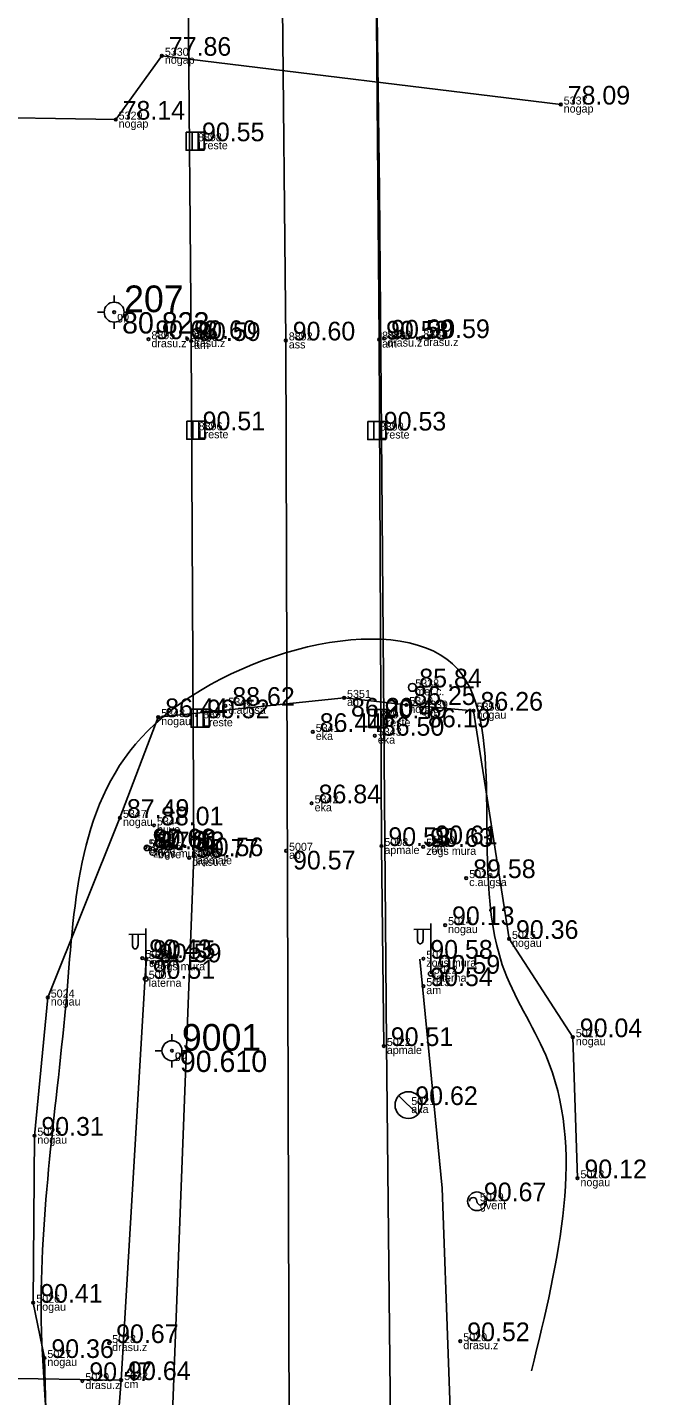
# Model space of a CAD drawing. Extents: x 614911 to 615803, y 262110 to 264311.
# Drawn here: x 615625.2 to 615648.4, y 263133.6 to 263184.9 of the extents above; entities that cross this region are included whole.
import ezdxf

# ---------------------------------------------------------------- set-up
doc = ezdxf.new("R2010")
doc.units = 0
for name, color, linetype in [('Default', 7, 'Continuous'), ('Level 12', 7, 'Continuous'), ('Level 14', 7, 'Continuous'), ('Level 19', 7, 'Continuous'), ('Level 27', 7, 'Continuous'), ('Level 31', 7, 'Continuous'), ('Level 37', 7, 'Continuous'), ('Level 44', 7, 'Continuous'), ('Level 48', 7, 'Continuous'), ('Level 53', 7, 'Continuous'), ('Level 54', 7, 'Continuous'), ('Level 57', 7, 'Continuous'), ('Level 58', 7, 'Continuous'), ('Level 7', 7, 'Continuous')]:
    doc.layers.add(name, color=color, linetype=linetype)

msp = doc.modelspace()

# ---------------------------------------------------------------- linework, layer by layer
at = {"layer": 'Default'}
for points in [[(615642.111, 263047.236), (615640.427, 263062.246), (615639.699, 263075.455), (615639.466, 263087.731), (615639.08, 263107.594), (615638.669, 263146.776), (615638.411, 263178.773), (615638.281, 263188.183)], [(615640.757, 263141.353), (615639.919, 263149.948)], [(615640.757, 263141.353), (615640.998, 263134.817), (615641.077, 263132.377), (615643.967, 263132.511)]]:
    msp.add_lwpolyline(points, dxfattribs=at)
msp.add_spline([(615625.966, 263122.745), (615626.114, 263129.516), (615625.726, 263136.404), (615626.677, 263148.613), (615629.722, 263158.508), (615641.149, 263161.013), (615643.012, 263149.736), (615644.64, 263146.351), (615644.11, 263134.516)], degree=3, dxfattribs=at)
at = {"layer": 'Level 12'}
for p, q in [((615639.13, 263144.823), (615639.848, 263144.127)), ((615639.489, 263144.475), (615639.488, 263144.474))]:
    msp.add_line(p, q, dxfattribs=at)
msp.add_circle((615639.489, 263144.475), 0.5, dxfattribs=at)
at = {"layer": 'Level 14'}
msp.add_circle((615639.638, 263160.134), 0.148, dxfattribs=at)
at = {"layer": 'Level 19'}
for p, q in [((615628.459, 263174.576), (615628.459, 263174.826)), ((615627.834, 263174.201), (615628.084, 263174.201)), ((615628.834, 263174.201), (615629.084, 263174.201)), ((615628.459, 263173.576), (615628.459, 263173.826)), ((615630.625, 263146.889), (615630.625, 263147.139)), ((615630, 263146.514), (615630.25, 263146.514)), ((615631, 263146.514), (615631.25, 263146.514)), ((615630.625, 263145.889), (615630.625, 263146.139))]:
    msp.add_line(p, q, dxfattribs=at)
for centre, radius in [((615628.459, 263174.201), 0.375), ((615628.459, 263174.201), 0.05), ((615630.625, 263146.514), 0.375), ((615630.625, 263146.514), 0.05)]:
    msp.add_circle(centre, radius, dxfattribs=at)
at = {"layer": 'Level 27'}
msp.add_circle((615642.061, 263140.868), 0.35, dxfattribs=at)
for centre, start, end in [((615641.921, 263140.868), 0, 180), ((615642.201, 263140.868), 180, 0)]:
    msp.add_arc(centre, 0.14, start, end, dxfattribs=at)
at = {"layer": 'Level 31'}
for points in [[(615645.203, 263181.984), (615630.246, 263183.814), (615628.514, 263181.419), (615622.47, 263181.52), (615621.763, 263178.82), (615619.334, 263173.437), (615618.468, 263173.209), (615614.263, 263169.507), (615607.963, 263162.509), (615614.672, 263141.896), (615612.332, 263134.683)], [(615639.412, 263159.474), (615637.078, 263159.739), (615630.111, 263159.019)], [(615639.412, 263159.474), (615641.935, 263159.261), (615643.264, 263150.705), (615645.656, 263147.02), (615645.831, 263141.731)], [(615630.111, 263159.019), (615628.675, 263155.243), (615625.969, 263148.507), (615625.467, 263143.326), (615625.424, 263137.065), (615625.842, 263134.993), (615625.948, 263131.109), (615625.2, 263127.266), (615625.864, 263116.003), (615625.339, 263108.896), (615618.12, 263017.928), (615614.008, 263002.211), (615611.608, 262992.724), (615610.318, 262984.066), (615604.711, 262969.009), (615598.026, 262946.805), (615590.694, 262924.523), (615584.099, 262903.018), (615578.016, 262882.248), (615571.57, 262862.909), (615571.479, 262861.254), (615568.795, 262854.862), (615562.238, 262831.156), (615556.487, 262814.508)]]:
    msp.add_lwpolyline(points, dxfattribs=at)
at = {"layer": 'Level 37'}
for p, q in [((615634.894, 263173.142), (615635.097, 263105.763)), ((615616.193, 263134.355), (615628.721, 263134.164))]:
    msp.add_line(p, q, dxfattribs=at)
for points in [[(615636.517, 263431.183), (615636.595, 263421.289), (615636.665, 263411.593), (615636.806, 263386.87), (615636.931, 263375.725), (615636.948, 263365.501), (615637.059, 263355.344), (615637.134, 263343.807), (615637.167, 263335.039), (615637.241, 263325.081), (615637.336, 263313.942), (615637.374, 263306.112), (615637.482, 263292.409), (615637.574, 263278.5), (615637.654, 263266.567), (615637.756, 263250.366), (615637.867, 263239.792), (615637.928, 263229.314), (615638.03, 263218.463), (615638.11, 263207.891), (615638.19, 263197.069), (615638.393, 263173.174)], [(615629.566, 263431.01), (615629.603, 263421.222), (615629.627, 263411.526), (615629.82, 263386.162), (615629.901, 263376.196), (615629.953, 263365.331), (615630.032, 263355.531), (615630.094, 263343.723), (615630.15, 263334.743), (615630.222, 263324.988), (615630.324, 263314.046), (615630.353, 263305.884), (615630.476, 263292.497), (615630.569, 263278.595), (615630.639, 263268.073), (615630.767, 263250.13), (615630.888, 263239.998), (615630.949, 263229.062), (615631.015, 263218.772), (615631.067, 263208.389), (615631.123, 263199.177), (615631.345, 263173.122)], [(615634.894, 263173.142), (615634.754, 263186.919), (615634.625, 263199.339), (615634.598, 263208.099), (615634.519, 263218.105)], [(615631.345, 263173.122), (615631.449, 263153.804), (615629.561, 263104.56), (615625.716, 263040.842), (615623.595, 263025.101), (615622.447, 263017.915), (615619.741, 263006.709), (615615.254, 262992.037), (615607.495, 262968.204)], [(615638.393, 263173.174), (615638.479, 263154.188), (615638.57, 263146.689)], [(615629.654, 263149.948), (615628.721, 263134.164), (615628.583, 263132.388), (615627.854, 263104.61), (615621.91, 263025.585), (615621.904, 263025.311), (615619.521, 263012.239), (615619.398, 263011.725), (615613.627, 262992.503), (615605.986, 262968.61), (615598.735, 262946.405), (615591.778, 262924.107), (615585.103, 262902.604), (615578.685, 262882.008), (615572.188, 262861.032), (615562.921, 262830.982), (615557.662, 262813.841), (615551.445, 262793.883), (615545.378, 262774.577), (615544.847, 262773.643)]]:
    msp.add_lwpolyline(points, dxfattribs=at)
at = {"layer": 'Level 44'}
for p, q in [((615629.642, 263149.21), (615629.642, 263151.093)), ((615640.33, 263151.065), (615639.695, 263151.06)), ((615639.83, 263151.061), (615639.83, 263150.669)), ((615640.04, 263151.063), (615640.04, 263150.669)), ((615640.33, 263149.398), (615640.33, 263151.281)), ((615629.642, 263150.877), (615629.007, 263150.872)), ((615629.142, 263150.873), (615629.142, 263150.481)), ((615629.352, 263150.875), (615629.352, 263150.481))]:
    msp.add_line(p, q, dxfattribs=at)
for centre in [(615640.33, 263149.398), (615629.642, 263149.21)]:
    msp.add_circle(centre, 0.09, dxfattribs=at)
for centre in [(615629.247, 263150.481), (615639.935, 263150.669)]:
    msp.add_ellipse(centre, major_axis=(0, 0.151), ratio=0.695971, start_param=1.570796, end_param=4.712389, dxfattribs=at)
at = {"layer": 'Level 48'}
for p, q in [((615631.377, 263180.947), (615631.377, 263180.272)), ((615631.602, 263180.947), (615631.602, 263180.272)), ((615631.402, 263170.112), (615631.402, 263169.437)), ((615631.627, 263170.112), (615631.627, 263169.437)), ((615638.194, 263170.101), (615638.194, 263169.426)), ((615638.419, 263170.101), (615638.419, 263169.426)), ((615631.566, 263159.314), (615631.566, 263158.639)), ((615631.791, 263159.314), (615631.791, 263158.639)), ((615638.226, 263159.309), (615638.226, 263158.634)), ((615638.451, 263159.309), (615638.451, 263158.634))]:
    msp.add_line(p, q, dxfattribs=at)
for points in [[(615631.152, 263180.947), (615631.827, 263180.947), (615631.827, 263180.272), (615631.152, 263180.272)], [(615631.177, 263170.112), (615631.852, 263170.112), (615631.852, 263169.437), (615631.177, 263169.437)], [(615637.969, 263170.101), (615638.644, 263170.101), (615638.644, 263169.426), (615637.969, 263169.426)], [(615631.341, 263159.314), (615632.016, 263159.314), (615632.016, 263158.639), (615631.341, 263158.639)], [(615638.001, 263159.309), (615638.676, 263159.309), (615638.676, 263158.634), (615638.001, 263158.634)]]:
    msp.add_lwpolyline(points, close=True, dxfattribs=at)
at = {"layer": 'Level 57'}
for centre in [(615630.246, 263183.814), (615645.203, 263181.984), (615628.514, 263181.419), (615629.743, 263173.187), (615631.2, 263173.193), (615631.345, 263173.122), (615634.894, 263173.142), (615638.393, 263173.174), (615638.583, 263173.21), (615639.941, 263173.23), (615637.078, 263159.739), (615632.627, 263159.443), (615639.412, 263159.474), (615639.966, 263159.336), (615641.935, 263159.261), (615630.111, 263159.019), (615635.905, 263158.464), (615638.233, 263158.322), (615635.863, 263155.788), (615628.675, 263155.243), (615629.952, 263154.961), (615629.639, 263154.137), (615629.81, 263154.061), (615629.989, 263154.027), (615634.904, 263154.008), (615638.479, 263154.188), (615640.048, 263154.156), (615640.236, 263154.253), (615631.269, 263153.745), (615631.449, 263153.804), (615641.659, 263152.984), (615640.866, 263151.222), (615643.264, 263150.705), (615629.513, 263149.984), (615629.654, 263149.948), (615640.051, 263149.963), (615629.88, 263149.826), (615640.051, 263148.934), (615625.969, 263148.507), (615645.656, 263147.02), (615638.57, 263146.689), (615625.467, 263143.326), (615645.831, 263141.731), (615625.424, 263137.065), (615628.271, 263135.552), (615641.437, 263135.623), (615625.842, 263134.993), (615627.266, 263134.128), (615628.721, 263134.164)]:
    msp.add_circle(centre, 0.05, dxfattribs=at)
at = {"layer": 'Level 58'}
for centre in [(615630.246, 263183.814), (615645.203, 263181.984), (615628.514, 263181.419), (615629.743, 263173.187), (615631.2, 263173.193), (615631.345, 263173.122), (615634.894, 263173.142), (615638.393, 263173.174), (615638.583, 263173.21), (615639.941, 263173.23), (615637.078, 263159.739), (615632.627, 263159.443), (615639.412, 263159.474), (615639.966, 263159.336), (615641.935, 263159.261), (615630.111, 263159.019), (615635.905, 263158.464), (615638.233, 263158.322), (615635.863, 263155.788), (615628.675, 263155.243), (615629.952, 263154.961), (615629.639, 263154.137), (615629.81, 263154.061), (615629.989, 263154.027), (615634.904, 263154.008), (615638.479, 263154.188), (615640.048, 263154.156), (615640.236, 263154.253), (615631.269, 263153.745), (615631.449, 263153.804), (615641.659, 263152.984), (615640.866, 263151.222), (615643.264, 263150.705), (615629.513, 263149.984), (615629.654, 263149.948), (615640.051, 263149.963), (615629.88, 263149.826), (615640.051, 263148.934), (615625.969, 263148.507), (615645.656, 263147.02), (615638.57, 263146.689), (615625.467, 263143.326), (615645.831, 263141.731), (615625.424, 263137.065), (615628.271, 263135.552), (615641.437, 263135.623), (615625.842, 263134.993), (615627.266, 263134.128), (615628.721, 263134.164)]:
    msp.add_circle(centre, 0.05, dxfattribs=at)
at = {"layer": 'Level 7'}
msp.add_circle((615629.683, 263154.115), 0.1, dxfattribs=at)

# ---------------------------------------------------------------- texts
at = {"layer": 'Level 19'}
for s, height, p in [(' 207', 1, (615628.459, 263174.201)), (' 80.823', 0.8, (615628.459, 263173.401)), (' 9001', 1, (615630.625, 263146.514)), (' 90.610', 0.8, (615630.625, 263145.714))]:
    msp.add_text(s, height=height, dxfattribs=at).set_placement(p)
at = {"layer": 'Level 27'}
msp.add_text(' 90.67', height=0.7, dxfattribs=at).set_placement((615642.061, 263140.868))
at = {"layer": 'Level 48'}
for s, p in [(' 90.55', (615631.49, 263180.609)), (' 90.51', (615631.515, 263169.774)), (' 90.53', (615638.307, 263169.763)), (' 90.52', (615631.679, 263158.976)), (' 90.49', (615638.339, 263158.971))]:
    msp.add_text(s, height=0.7, dxfattribs=at).set_placement(p)
at = {"layer": 'Level 53'}
for s, p in [(' nogap', (615630.246, 263183.514)), (' nogap', (615645.203, 263181.684)), (' nogap', (615628.514, 263181.119)), (' Lreste', (615631.49, 263180.309)), (' gp', (615628.459, 263173.901)), (' drasu.z', (615629.743, 263172.887)), (' drasu.z', (615631.2, 263172.893)), (' am', (615631.345, 263172.822)), (' ass', (615634.894, 263172.842)), (' am', (615638.393, 263172.874)), (' drasu.z', (615638.583, 263172.91)), (' drasu.z', (615639.941, 263172.93)), (' Lreste', (615631.515, 263169.474)), (' Lreste', (615638.307, 263169.463)), (' met.c.', (615639.638, 263159.834)), (' c.augsa', (615632.627, 263159.143)), (' ap', (615637.078, 263159.439)), (' nogau', (615639.412, 263159.174)), (' ap', (615639.966, 263159.036)), (' nogau', (615641.935, 263158.961)), (' nogau', (615630.111, 263158.719)), (' Lreste', (615631.679, 263158.676)), (' Lreste', (615638.339, 263158.671)), (' eka', (615635.905, 263158.164)), (' eka', (615638.233, 263158.022)), (' eka', (615635.863, 263155.488)), (' nogau', (615628.675, 263154.943)), (' buve', (615629.952, 263154.661)), (' cm', (615629.639, 263153.837)), (' el.iev', (615629.683, 263153.815)), (' buve', (615629.989, 263153.727)), (' apmale', (615638.479, 263153.888)), (' zogs mura', (615640.048, 263153.856)), (' cm', (615640.236, 263153.953)), (' zogs mura', (615629.81, 263153.761)), (' drasu.z', (615631.269, 263153.445)), (' apmale', (615631.449, 263153.504)), (' ap', (615634.904, 263153.708)), (' c.augsa', (615641.659, 263152.684)), (' nogau', (615640.866, 263150.922)), (' nogau', (615643.264, 263150.405)), (' nogau', (615629.513, 263149.684)), (' cm', (615629.654, 263149.648)), (' zogs mura', (615629.88, 263149.526)), (' zogs mura', (615640.051, 263149.663)), (' laterna', (615629.642, 263148.91)), (' laterna', (615640.33, 263149.098)), (' nogau', (615625.969, 263148.207)), (' am', (615640.051, 263148.634)), (' nogau', (615645.656, 263146.72)), (' gp', (615630.625, 263146.214)), (' pp', (615630.625, 263146.214)), (' apmale', (615638.57, 263146.389)), (' aka', (615639.489, 263144.175)), (' nogau', (615625.467, 263143.026)), (' nogau', (615645.831, 263141.431)), (' gvent', (615642.061, 263140.568)), (' nogau', (615625.424, 263136.765)), (' drasu.z', (615641.437, 263135.323)), (' drasu.z', (615628.271, 263135.252)), (' nogau', (615625.842, 263134.693)), (' drasu.z', (615627.266, 263133.828)), (' cm', (615628.721, 263133.864))]:
    msp.add_text(s, height=0.3, dxfattribs=at).set_placement(p)
at = {"layer": 'Level 54'}
for s, p in [(' 5330', (615630.246, 263183.814)), (' 5337', (615645.203, 263181.984)), (' 5329', (615628.514, 263181.419)), (' 8898', (615631.49, 263180.609)), (' 8895', (615629.743, 263173.187)), (' 8894', (615631.2, 263173.193)), (' 8893', (615631.345, 263173.122)), (' 8892', (615634.894, 263173.142)), (' 8889', (615638.393, 263173.174)), (' 8888', (615638.583, 263173.21)), (' 8887', (615639.941, 263173.23)), (' 8896', (615631.515, 263169.774)), (' 8890', (615638.307, 263169.763)), (' 5338', (615639.638, 263160.134)), (' 5340', (615632.627, 263159.443)), (' 5351', (615637.078, 263159.739)), (' 5349', (615639.412, 263159.474)), (' 5348', (615630.111, 263159.019)), (' 8897', (615631.679, 263158.976)), (' 8891', (615638.339, 263158.971)), (' 5339', (615639.966, 263159.336)), (' 5350', (615641.935, 263159.261)), (' 5341', (615635.905, 263158.464)), (' 5343', (615638.233, 263158.322)), (' 5342', (615635.863, 263155.788)), (' 5347', (615628.675, 263155.243)), (' 5344', (615629.952, 263154.961)), (' 5010', (615640.236, 263154.253)), (' 5004', (615629.639, 263154.137)), (' 5346', (615629.683, 263154.115)), (' 5005', (615629.81, 263154.061)), (' 5345', (615629.989, 263154.027)), (' 5003', (615631.269, 263153.745)), (' 5006', (615631.449, 263153.804)), (' 5007', (615634.904, 263154.008)), (' 5008', (615638.479, 263154.188)), (' 5009', (615640.048, 263154.156)), (' 5016', (615641.659, 263152.984)), (' 5014', (615640.866, 263151.222)), (' 5015', (615643.264, 263150.705)), (' 5023', (615629.513, 263149.984)), (' 5002', (615629.654, 263149.948)), (' 5000', (615629.88, 263149.826)), (' 5011', (615640.051, 263149.963)), (' 5001', (615629.642, 263149.21)), (' 5012', (615640.33, 263149.398)), (' 5013', (615640.051, 263148.934)), (' 5024', (615625.969, 263148.507)), (' 5022', (615638.57, 263146.689)), (' 5017', (615645.656, 263147.02)), (' 5021', (615639.489, 263144.475)), (' 5025', (615625.467, 263143.326)), (' 5018', (615645.831, 263141.731)), (' 5019', (615642.061, 263140.868)), (' 5026', (615625.424, 263137.065)), (' 5028', (615628.271, 263135.552)), (' 5020', (615641.437, 263135.623)), (' 5027', (615625.842, 263134.993)), (' 5029', (615627.266, 263134.128)), (' 5032', (615628.721, 263134.164))]:
    msp.add_text(s, height=0.3, dxfattribs=at).set_placement(p)
at = {"layer": 'Level 58'}
for s, p in [(' 77.86', (615630.246, 263183.814)), (' 78.09', (615645.203, 263181.984)), (' 78.14', (615628.514, 263181.419)), (' 90.63', (615629.743, 263173.187)), (' 90.60', (615631.2, 263173.193)), (' 90.59', (615631.345, 263173.122)), (' 90.60', (615634.894, 263173.142)), (' 90.53', (615638.393, 263173.174)), (' 90.59', (615638.583, 263173.21)), (' 90.59', (615639.941, 263173.23)), (' 85.84', (615639.638, 263160.134)), (' 86.44', (615630.111, 263159.019)), (' 88.62', (615632.627, 263159.443)), (' 86.20', (615637.078, 263159.039)), (' 86.25', (615639.412, 263159.474)), (' 86.26', (615641.935, 263159.261)), (' 86.44', (615635.905, 263158.464)), (' 86.19', (615639.966, 263158.636)), (' 86.50', (615638.233, 263158.322)), (' 86.84', (615635.863, 263155.788)), (' 87.49', (615628.675, 263155.243)), (' 88.01', (615629.952, 263154.961)), (' 90.60', (615629.639, 263154.137)), (' 87.86', (615629.683, 263154.115)), (' 90.61', (615629.81, 263154.061)), (' 87.92', (615629.989, 263154.027)), (' 90.53', (615638.479, 263154.188)), (' 90.63', (615640.048, 263154.156)), (' 90.61', (615640.236, 263154.253)), (' 90.77', (615631.269, 263153.745)), (' 90.56', (615631.449, 263153.804)), (' 90.57', (615634.904, 263153.308)), (' 89.58', (615641.659, 263152.984)), (' 90.13', (615640.866, 263151.222)), (' 90.36', (615643.264, 263150.705)), (' 90.43', (615629.513, 263149.984)), (' 90.55', (615629.654, 263149.948)), (' 90.59', (615629.88, 263149.826)), (' 90.58', (615640.051, 263149.963)), (' 90.59', (615640.33, 263149.398)), (' 90.51', (615629.642, 263149.21)), (' 90.54', (615640.051, 263148.934)), (' 90.51', (615638.57, 263146.689)), (' 90.04', (615645.656, 263147.02)), (' 90.62', (615639.489, 263144.475)), (' 90.31', (615625.467, 263143.326)), (' 90.12', (615645.831, 263141.731)), (' 90.41', (615625.424, 263137.065)), (' 90.67', (615628.271, 263135.552)), (' 90.52', (615641.437, 263135.623)), (' 90.36', (615625.842, 263134.993)), (' 90.47', (615627.266, 263134.128)), (' 90.64', (615628.721, 263134.164))]:
    msp.add_text(s, height=0.7, dxfattribs=at).set_placement(p)
at = {"layer": 'Level 7'}
msp.add_text(' el.', height=0.7, dxfattribs=at).set_placement((615629.683, 263154.115))

doc.saveas('drawing.dxf')
